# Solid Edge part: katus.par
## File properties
Author: Georg
Template: Iso Metric Part.par
Last saved by: Georg
Revision: 7
Application: Solid Edge
Accuracy: 0,990
Face Style: Model Default
Fill Style: Normal
Coef. of Thermal Exp: 0.0
Thermal Conductivity: 0.0
Specific Heat: 0.0
Modulus of Elasticity: 0.0
Poisson's Ratio: 0.0
Yield Stress: 0.0
Ultimate Stress: 0.0
Elongation: 0.0
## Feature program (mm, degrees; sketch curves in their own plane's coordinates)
make body feature "unnamed MakeBodyFeature 1"
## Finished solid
Body 1: solid body, 3 faces, 3 edges, 2 vertices.
  Faces by surface: spline 2, plane 1
  Edges by curve: curve on surface 2, spline 1
Body 2: solid body, 3 faces, 3 edges, 2 vertices.
  Faces by surface: spline 2, plane 1
  Edges by curve: curve on surface 2, spline 1
Bounding box of the edges (mm; curved faces can reach further): 679.999 x 1310.381 x 354.130, from (-339.9997, 1267.2018, 0) to (339.9996, 2577.5825, 354.1304).
Planar faces by outward normal: -z 2
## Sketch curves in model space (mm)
spline (0, 1267.2018, 0) -> (0, 1963.3705, 325.2207) -> (0, 2567.2018, 0)
spline (0, 2250, 353.6387) -> (-266.3299, 2250, 216.1953) -> (-292.0556, 2250, 0)
spline (0, 1700, 267.5905) -> (-262.0783, 1700, 166.2732) -> (-320.456, 1700, 0)
spline (0, 2567.2018, 0) -> (-339.6184, 1886.4159, 0) -> (0, 1267.2018, 0)
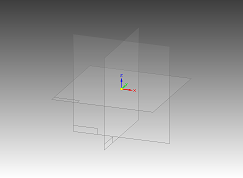
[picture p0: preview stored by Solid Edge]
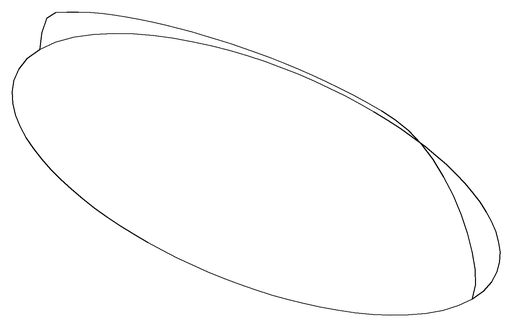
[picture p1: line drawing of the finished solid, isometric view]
